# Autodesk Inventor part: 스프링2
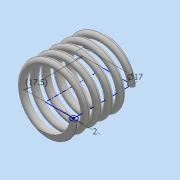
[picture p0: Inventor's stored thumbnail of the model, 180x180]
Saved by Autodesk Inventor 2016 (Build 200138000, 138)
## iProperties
Created: 2019-11
Part Number: 스프링2
Material: 일반
Document SubType Name: Modeling
Designer: user
Density: 1 g/cm^3
Appearance: 기본값
Mass: 0.819704 g
Surface Area: 16.7049 cm^2
Volume: 0.819704 cm^3
Author: user
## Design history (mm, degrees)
sketch "스케치1"
  geometry: L1 (0, 0)-(8.5, 0); L2 (8.5, 0)-(8.5, 17.5); L3 (8.5, 17.5)-(0, 17.5); L4 (0, 17.5)-(0, 0); C1 r 1 at (8.5, 0)
  constraints: 8 end point, 2 parallel, 1 centre point, 1 coincident, 1 horizontal, 1 perpendicular
  dimensions: "d0" = 17 diameter of L2 L4; "d1" = 17.5 distance between parallel lines of L1 L3 (derived); "d2" = 2 diameter of C1
feature "코일1" sketch "스케치1" pitch "d3" = 10; turns "d5" = 5; dims "d4" = 17.5 (= d1), "d6" = 0, angle "d7" = 90 deg, angle "d8" = 90 deg, "d9" = 0, "d10" = 0
sketch "스케치2"
  geometry: L1 (-11.228, 0)-(11.228, 0); L2 (11.228, 0)-(11.228, 17.5); L3 (11.228, 17.5)-(-11.228, 17.5); L4 (-11.228, 17.5)-(-11.228, 0); 2 further points
  constraints: 8 end point, 2 parallel, 1 coincident, 1 horizontal, 1 midpoint, 1 perpendicular
  dimensions: "d11" = 17.5 distance between parallel lines of L1 L3 (= d1); "d12" = 22.45649 distance between parallel lines of L2 L4
extrude "돌출1" sketch "스케치2" stored distance "d13" = 42.25; taper "d14" = 0 deg
node "솔리드1"
